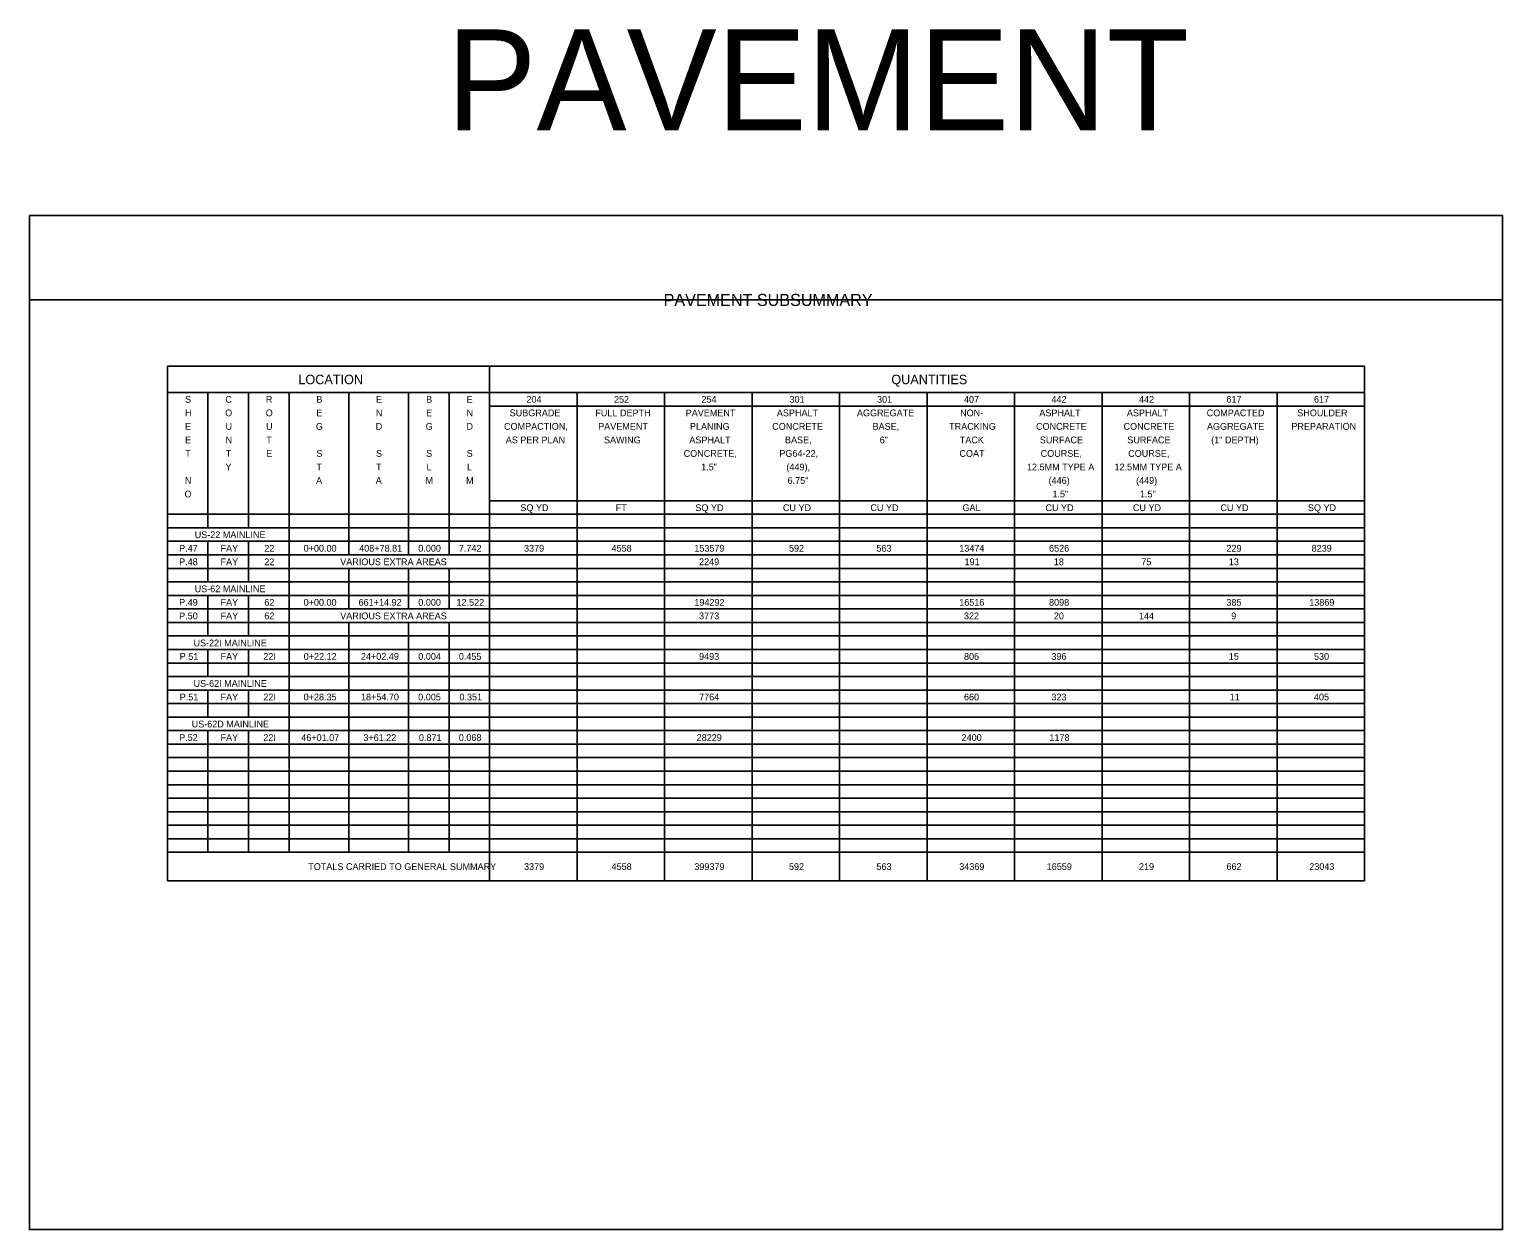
# Model space of a CAD drawing. Extents: x 12522 to 13018, y 1124 to 1902.
# Drawn here: x 12797.22 to 12827.72, y 1828.79 to 1853.64 of the extents above; entities that cross this region are included whole.
import ezdxf

# ---------------------------------------------------------------- set-up
doc = ezdxf.new("R2010")
doc.units = 0
for name, color, linetype in [('SC_Scratch1', 7, 'Continuous'), ('SH_Data', 7, 'Continuous'), ('SH_Text', 7, 'Continuous')]:
    doc.layers.add(name, color=color, linetype=linetype)

msp = doc.modelspace()

# ---------------------------------------------------------------- linework, layer by layer
at = {"layer": 'SC_Scratch1'}
msp.add_line((12827.724, 1848.043), (12797.224, 1848.043), dxfattribs=at)
msp.add_lwpolyline([(12797.224, 1849.791), (12827.724, 1849.791), (12827.724, 1828.791), (12797.224, 1828.791)], close=True, dxfattribs=at)
at = {"layer": 'SH_Data'}
for p, q in [((12800.08, 1846.668), (12824.868, 1846.668)), ((12800.08, 1846.668), (12800.08, 1836.011)), ((12806.751, 1846.668), (12806.751, 1836.011)), ((12824.868, 1846.668), (12824.868, 1836.011)), ((12800.08, 1846.124), (12824.868, 1846.124)), ((12800.92, 1846.124), (12800.92, 1843.324)), ((12801.76, 1846.124), (12801.76, 1843.324)), ((12802.6, 1846.124), (12802.6, 1836.604)), ((12803.835, 1846.124), (12803.835, 1842.764)), ((12805.071, 1846.124), (12805.071, 1842.764)), ((12805.911, 1846.124), (12805.911, 1842.764)), ((12808.562, 1846.124), (12808.562, 1836.011)), ((12810.374, 1846.124), (12810.374, 1836.011)), ((12812.186, 1846.124), (12812.186, 1836.011)), ((12813.998, 1846.124), (12813.998, 1836.011)), ((12815.809, 1846.124), (12815.809, 1836.011)), ((12817.621, 1846.124), (12817.621, 1836.011)), ((12819.433, 1846.124), (12819.433, 1836.011)), ((12821.245, 1846.124), (12821.245, 1836.011)), ((12823.057, 1846.124), (12823.057, 1836.011)), ((12806.751, 1845.844), (12824.868, 1845.844)), ((12806.751, 1843.884), (12824.868, 1843.884)), ((12800.08, 1843.604), (12824.868, 1843.604)), ((12800.08, 1843.324), (12824.868, 1843.324)), ((12800.08, 1843.044), (12824.868, 1843.044)), ((12800.92, 1843.044), (12800.92, 1842.204)), ((12801.76, 1843.044), (12801.76, 1842.204)), ((12800.08, 1842.764), (12824.868, 1842.764)), ((12800.08, 1842.484), (12824.868, 1842.484)), ((12800.08, 1842.204), (12824.868, 1842.204)), ((12803.835, 1842.484), (12803.835, 1841.644)), ((12805.071, 1842.484), (12805.071, 1841.644)), ((12805.911, 1842.484), (12805.911, 1841.644)), ((12800.08, 1841.924), (12824.868, 1841.924)), ((12800.92, 1841.924), (12800.92, 1841.084)), ((12801.76, 1841.924), (12801.76, 1841.084)), ((12800.08, 1841.644), (12824.868, 1841.644)), ((12800.08, 1841.364), (12824.868, 1841.364)), ((12803.835, 1841.364), (12803.835, 1836.604)), ((12805.071, 1841.364), (12805.071, 1836.604)), ((12805.911, 1841.364), (12805.911, 1836.604)), ((12800.08, 1841.084), (12824.868, 1841.084)), ((12800.08, 1840.804), (12824.868, 1840.804)), ((12800.92, 1840.804), (12800.92, 1840.244)), ((12801.76, 1840.804), (12801.76, 1840.244)), ((12800.08, 1840.524), (12824.868, 1840.524)), ((12800.08, 1840.244), (12824.868, 1840.244)), ((12800.08, 1839.964), (12824.868, 1839.964)), ((12800.92, 1839.964), (12800.92, 1839.404)), ((12801.76, 1839.964), (12801.76, 1839.404)), ((12800.08, 1839.684), (12824.868, 1839.684)), ((12800.08, 1839.404), (12824.868, 1839.404)), ((12800.08, 1839.124), (12824.868, 1839.124)), ((12800.92, 1839.124), (12800.92, 1836.604)), ((12801.76, 1839.124), (12801.76, 1836.604)), ((12800.08, 1838.844), (12824.868, 1838.844)), ((12800.08, 1838.564), (12824.868, 1838.564)), ((12800.08, 1838.284), (12824.868, 1838.284)), ((12800.08, 1838.004), (12824.868, 1838.004)), ((12800.08, 1837.724), (12824.868, 1837.724)), ((12800.08, 1837.444), (12824.868, 1837.444)), ((12800.08, 1837.164), (12824.868, 1837.164)), ((12800.08, 1836.884), (12824.868, 1836.884)), ((12800.08, 1836.604), (12824.868, 1836.604)), ((12800.08, 1836.011), (12824.868, 1836.011))]:
    msp.add_line(p, q, dxfattribs=at)

# ---------------------------------------------------------------- texts
at = {"layer": 'SC_Scratch1'}
msp.add_text('PAVEMENT', height=2.0896, dxfattribs=at).set_placement((12805.861, 1851.555))
at = {"layer": 'SH_Text'}
for s, height, p in [('PAVEMENT SUBSUMMARY', 0.25, (12810.353, 1847.918)), ('LOCATION', 0.196, (12802.791, 1846.298)), ('QUANTITIES', 0.196, (12815.069, 1846.298)), ('S', 0.14, (12800.446, 1845.914)), ('C', 0.14, (12801.28, 1845.914)), ('R', 0.14, (12802.118, 1845.914)), ('B', 0.14, (12803.164, 1845.914)), ('E', 0.14, (12804.399, 1845.914)), ('B', 0.14, (12805.437, 1845.914)), ('E', 0.14, (12806.277, 1845.914)), ('204', 0.14, (12807.514, 1845.914)), ('252', 0.14, (12809.326, 1845.914)), ('254', 0.14, (12811.138, 1845.914)), ('301', 0.14, (12812.961, 1845.914)), ('301', 0.14, (12814.773, 1845.914)), ('407', 0.14, (12816.573, 1845.914)), ('442', 0.14, (12818.385, 1845.914)), ('442', 0.14, (12820.197, 1845.914)), ('617', 0.14, (12822.008, 1845.914)), ('617', 0.14, (12823.82, 1845.914)), ('H', 0.14, (12800.444, 1845.634)), ('O', 0.14, (12801.276, 1845.634)), ('O', 0.14, (12802.116, 1845.634)), ('E', 0.14, (12803.164, 1845.634)), ('N', 0.14, (12804.397, 1845.634)), ('E', 0.14, (12805.437, 1845.634)), ('N', 0.14, (12806.274, 1845.634)), ('SUBGRADE', 0.14, (12807.167, 1845.634)), ('FULL DEPTH', 0.14, (12808.941, 1845.634)), ('PAVEMENT', 0.14, (12810.811, 1845.634)), ('ASPHALT', 0.14, (12812.699, 1845.634)), ('AGGREGATE', 0.14, (12814.357, 1845.634)), ('NON-', 0.14, (12816.493, 1845.634)), ('ASPHALT', 0.14, (12818.134, 1845.634)), ('ASPHALT', 0.14, (12819.946, 1845.634)), ('COMPACTED', 0.14, (12821.599, 1845.634)), ('SHOULDER', 0.14, (12823.474, 1845.634)), ('E', 0.14, (12800.446, 1845.354)), ('U', 0.14, (12801.284, 1845.354)), ('U', 0.14, (12802.124, 1845.354)), ('G', 0.14, (12803.155, 1845.354)), ('D', 0.14, (12804.394, 1845.354)), ('G', 0.14, (12805.428, 1845.354)), ('D', 0.14, (12806.272, 1845.354)), ('COMPACTION,', 0.14, (12807.05, 1845.354)), ('PAVEMENT', 0.14, (12808.999, 1845.354)), ('PLANING', 0.14, (12810.899, 1845.354)), ('CONCRETE', 0.14, (12812.603, 1845.354)), (' BASE,', 0.14, (12814.628, 1845.354)), ('TRACKING', 0.14, (12816.266, 1845.354)), (' CONCRETE', 0.14, (12818.013, 1845.354)), (' CONCRETE', 0.14, (12819.825, 1845.354)), ('AGGREGATE', 0.14, (12821.604, 1845.354)), ('PREPARATION', 0.14, (12823.352, 1845.354)), ('E', 0.14, (12800.446, 1845.074)), ('N', 0.14, (12801.284, 1845.074)), ('T', 0.14, (12802.128, 1845.074)), ('AS PER PLAN', 0.14, (12807.086, 1845.074)), ('SAWING', 0.14, (12809.12, 1845.074)), ('ASPHALT', 0.14, (12810.887, 1845.074)), (' BASE,', 0.14, (12812.816, 1845.074)), ('6"', 0.14, (12814.828, 1845.074)), ('TACK', 0.14, (12816.487, 1845.074)), (' SURFACE', 0.14, (12818.092, 1845.074)), (' SURFACE', 0.14, (12819.903, 1845.074)), ('(1" DEPTH)', 0.14, (12821.692, 1845.074)), ('T', 0.14, (12800.448, 1844.794)), ('Y', 0.14, (12801.282, 1844.514)), ('T', 0.14, (12801.288, 1844.794)), ('E', 0.14, (12802.126, 1844.794)), ('T', 0.14, (12803.166, 1844.514)), ('S', 0.14, (12803.164, 1844.794)), ('T', 0.14, (12804.401, 1844.514)), ('S', 0.14, (12804.399, 1844.794)), ('S', 0.14, (12805.437, 1844.794)), ('L', 0.14, (12805.445, 1844.514)), ('S', 0.14, (12806.277, 1844.794)), ('L', 0.14, (12806.285, 1844.514)), ('CONCRETE,', 0.14, (12810.769, 1844.794)), ('1.5"', 0.14, (12811.131, 1844.514)), (' PG64-22,', 0.14, (12812.699, 1844.794)), (' (449),', 0.14, (12812.845, 1844.514)), ('COAT', 0.14, (12816.479, 1844.794)), ('12.5MM TYPE A', 0.14, (12817.878, 1844.514)), (' COURSE,', 0.14, (12818.109, 1844.794)), ('12.5MM TYPE A', 0.14, (12819.69, 1844.514)), (' COURSE,', 0.14, (12819.921, 1844.794)), ('N', 0.14, (12800.444, 1844.234)), ('A', 0.14, (12803.159, 1844.234)), ('A', 0.14, (12804.394, 1844.234)), ('M', 0.14, (12805.424, 1844.234)), ('M', 0.14, (12806.264, 1844.234)), (' 6.75"', 0.14, (12812.869, 1844.234)), ('(446)', 0.14, (12818.325, 1844.234)), ('(449)', 0.14, (12820.137, 1844.234)), ('O', 0.14, (12800.436, 1843.954)), (' 1.5"', 0.14, (12818.353, 1843.954)), (' 1.5"', 0.14, (12820.165, 1843.954)), ('SQ YD', 0.14, (12807.389, 1843.67)), ('FT', 0.14, (12809.363, 1843.67)), ('SQ YD', 0.14, (12811.012, 1843.67)), ('CU YD', 0.14, (12812.824, 1843.67)), ('CU YD', 0.14, (12814.636, 1843.67)), ('GAL', 0.14, (12816.542, 1843.67)), ('CU YD', 0.14, (12818.26, 1843.67)), ('CU YD', 0.14, (12820.071, 1843.67)), ('CU YD', 0.14, (12821.883, 1843.67)), ('SQ YD', 0.14, (12823.695, 1843.67)), ('US-22 MAINLINE', 0.14, (12800.645, 1843.11)), ('P.47', 0.14, (12800.323, 1842.83)), ('FAY', 0.14, (12801.181, 1842.83)), ('22', 0.14, (12802.087, 1842.83)), ('0+00.00', 0.14, (12802.901, 1842.83)), ('408+78.81', 0.14, (12804.051, 1842.83)), ('0.000', 0.14, (12805.275, 1842.83)), ('7.742', 0.14, (12806.115, 1842.83)), ('3379', 0.14, (12807.465, 1842.83)), ('4558', 0.14, (12809.276, 1842.83)), ('153579', 0.14, (12810.99, 1842.83)), ('592', 0.14, (12812.95, 1842.83)), ('563', 0.14, (12814.761, 1842.83)), ('13474', 0.14, (12816.475, 1842.83)), ('6526', 0.14, (12818.335, 1842.83)), ('229', 0.14, (12822.008, 1842.83)), ('8239', 0.14, (12823.771, 1842.83)), ('P.48', 0.14, (12800.323, 1842.55)), ('FAY', 0.14, (12801.181, 1842.55)), ('22', 0.14, (12802.087, 1842.55)), ('VARIOUS EXTRA AREAS', 0.14, (12803.659, 1842.55)), ('2249', 0.14, (12811.088, 1842.55)), ('191', 0.14, (12816.585, 1842.55)), ('18', 0.14, (12818.433, 1842.55)), ('75', 0.14, (12820.245, 1842.55)), ('13', 0.14, (12822.057, 1842.55)), ('US-62 MAINLINE', 0.14, (12800.645, 1841.99)), ('P.49', 0.14, (12800.323, 1841.71)), ('FAY', 0.14, (12801.181, 1841.71)), ('62', 0.14, (12802.087, 1841.71)), ('0+00.00', 0.14, (12802.901, 1841.71)), ('661+14.92', 0.14, (12804.039, 1841.71)), ('0.000', 0.14, (12805.275, 1841.71)), ('12.522', 0.14, (12806.066, 1841.71)), ('194292', 0.14, (12810.991, 1841.71)), ('16516', 0.14, (12816.475, 1841.71)), ('8098', 0.14, (12818.335, 1841.71)), ('385', 0.14, (12822.007, 1841.71)), ('13869', 0.14, (12823.722, 1841.71)), ('P.50', 0.14, (12800.323, 1841.43)), ('FAY', 0.14, (12801.181, 1841.43)), ('62', 0.14, (12802.087, 1841.43)), ('VARIOUS EXTRA AREAS', 0.14, (12803.659, 1841.43)), ('3773', 0.14, (12811.088, 1841.43)), ('322', 0.14, (12816.573, 1841.43)), ('20', 0.14, (12818.434, 1841.43)), ('144', 0.14, (12820.196, 1841.43)), ('9', 0.14, (12822.106, 1841.43)), ('US-22I MAINLINE', 0.14, (12800.621, 1840.87)), ('P.51', 0.14, (12800.335, 1840.59)), ('FAY', 0.14, (12801.181, 1840.59)), ('22I', 0.14, (12802.066, 1840.59)), ('0+22.12', 0.14, (12802.902, 1840.59)), ('24+02.49', 0.14, (12804.087, 1840.59)), ('0.004', 0.14, (12805.275, 1840.59)), ('0.455', 0.14, (12806.114, 1840.59)), ('9493', 0.14, (12811.088, 1840.59)), ('806', 0.14, (12816.573, 1840.59)), ('396', 0.14, (12818.384, 1840.59)), ('15', 0.14, (12822.056, 1840.59)), ('530', 0.14, (12823.82, 1840.59)), ('US-62I MAINLINE', 0.14, (12800.621, 1840.03)), ('P.51', 0.14, (12800.335, 1839.75)), ('FAY', 0.14, (12801.181, 1839.75)), ('22I', 0.14, (12802.066, 1839.75)), ('0+28.35', 0.14, (12802.901, 1839.75)), ('18+54.70', 0.14, (12804.088, 1839.75)), ('0.005', 0.14, (12805.274, 1839.75)), ('0.351', 0.14, (12806.127, 1839.75)), ('7764', 0.14, (12811.089, 1839.75)), ('660', 0.14, (12816.573, 1839.75)), ('323', 0.14, (12818.384, 1839.75)), ('11', 0.14, (12822.076, 1839.75)), ('405', 0.14, (12823.819, 1839.75)), ('US-62D MAINLINE', 0.14, (12800.582, 1839.19)), ('P.52', 0.14, (12800.324, 1838.91)), ('FAY', 0.14, (12801.181, 1838.91)), ('22I', 0.14, (12802.066, 1838.91)), ('46+01.07', 0.14, (12802.852, 1838.91)), ('3+61.22', 0.14, (12804.137, 1838.91)), ('0.871', 0.14, (12805.287, 1838.91)), ('0.068', 0.14, (12806.114, 1838.91)), ('28229', 0.14, (12811.039, 1838.91)), ('2400', 0.14, (12816.524, 1838.91)), ('1178', 0.14, (12818.342, 1838.91)), ('TOTALS CARRIED TO GENERAL SUMMARY', 0.14, (12802.997, 1836.238)), ('3379', 0.14, (12807.465, 1836.238)), ('4558', 0.14, (12809.276, 1836.238)), ('399379', 0.14, (12810.99, 1836.238)), ('592', 0.14, (12812.95, 1836.238)), ('563', 0.14, (12814.761, 1836.238)), ('34369', 0.14, (12816.475, 1836.238)), ('16559', 0.14, (12818.286, 1836.238)), ('219', 0.14, (12820.196, 1836.238)), ('662', 0.14, (12822.009, 1836.238)), ('23043', 0.14, (12823.722, 1836.238))]:
    msp.add_text(s, height=height, dxfattribs=at).set_placement(p)

doc.saveas('drawing.dxf')
